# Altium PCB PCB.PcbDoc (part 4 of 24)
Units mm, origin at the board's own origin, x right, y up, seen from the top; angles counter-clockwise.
Board outline 100 x 160 mm, 10 copper layers (TOP_L1, L2, L3, L4, L5, L6, L7, L8, L9, BOTTOM_L10), stack 1.946 mm thick; 1358 components, 1149 nets, 6777 pads, 10914 vias.
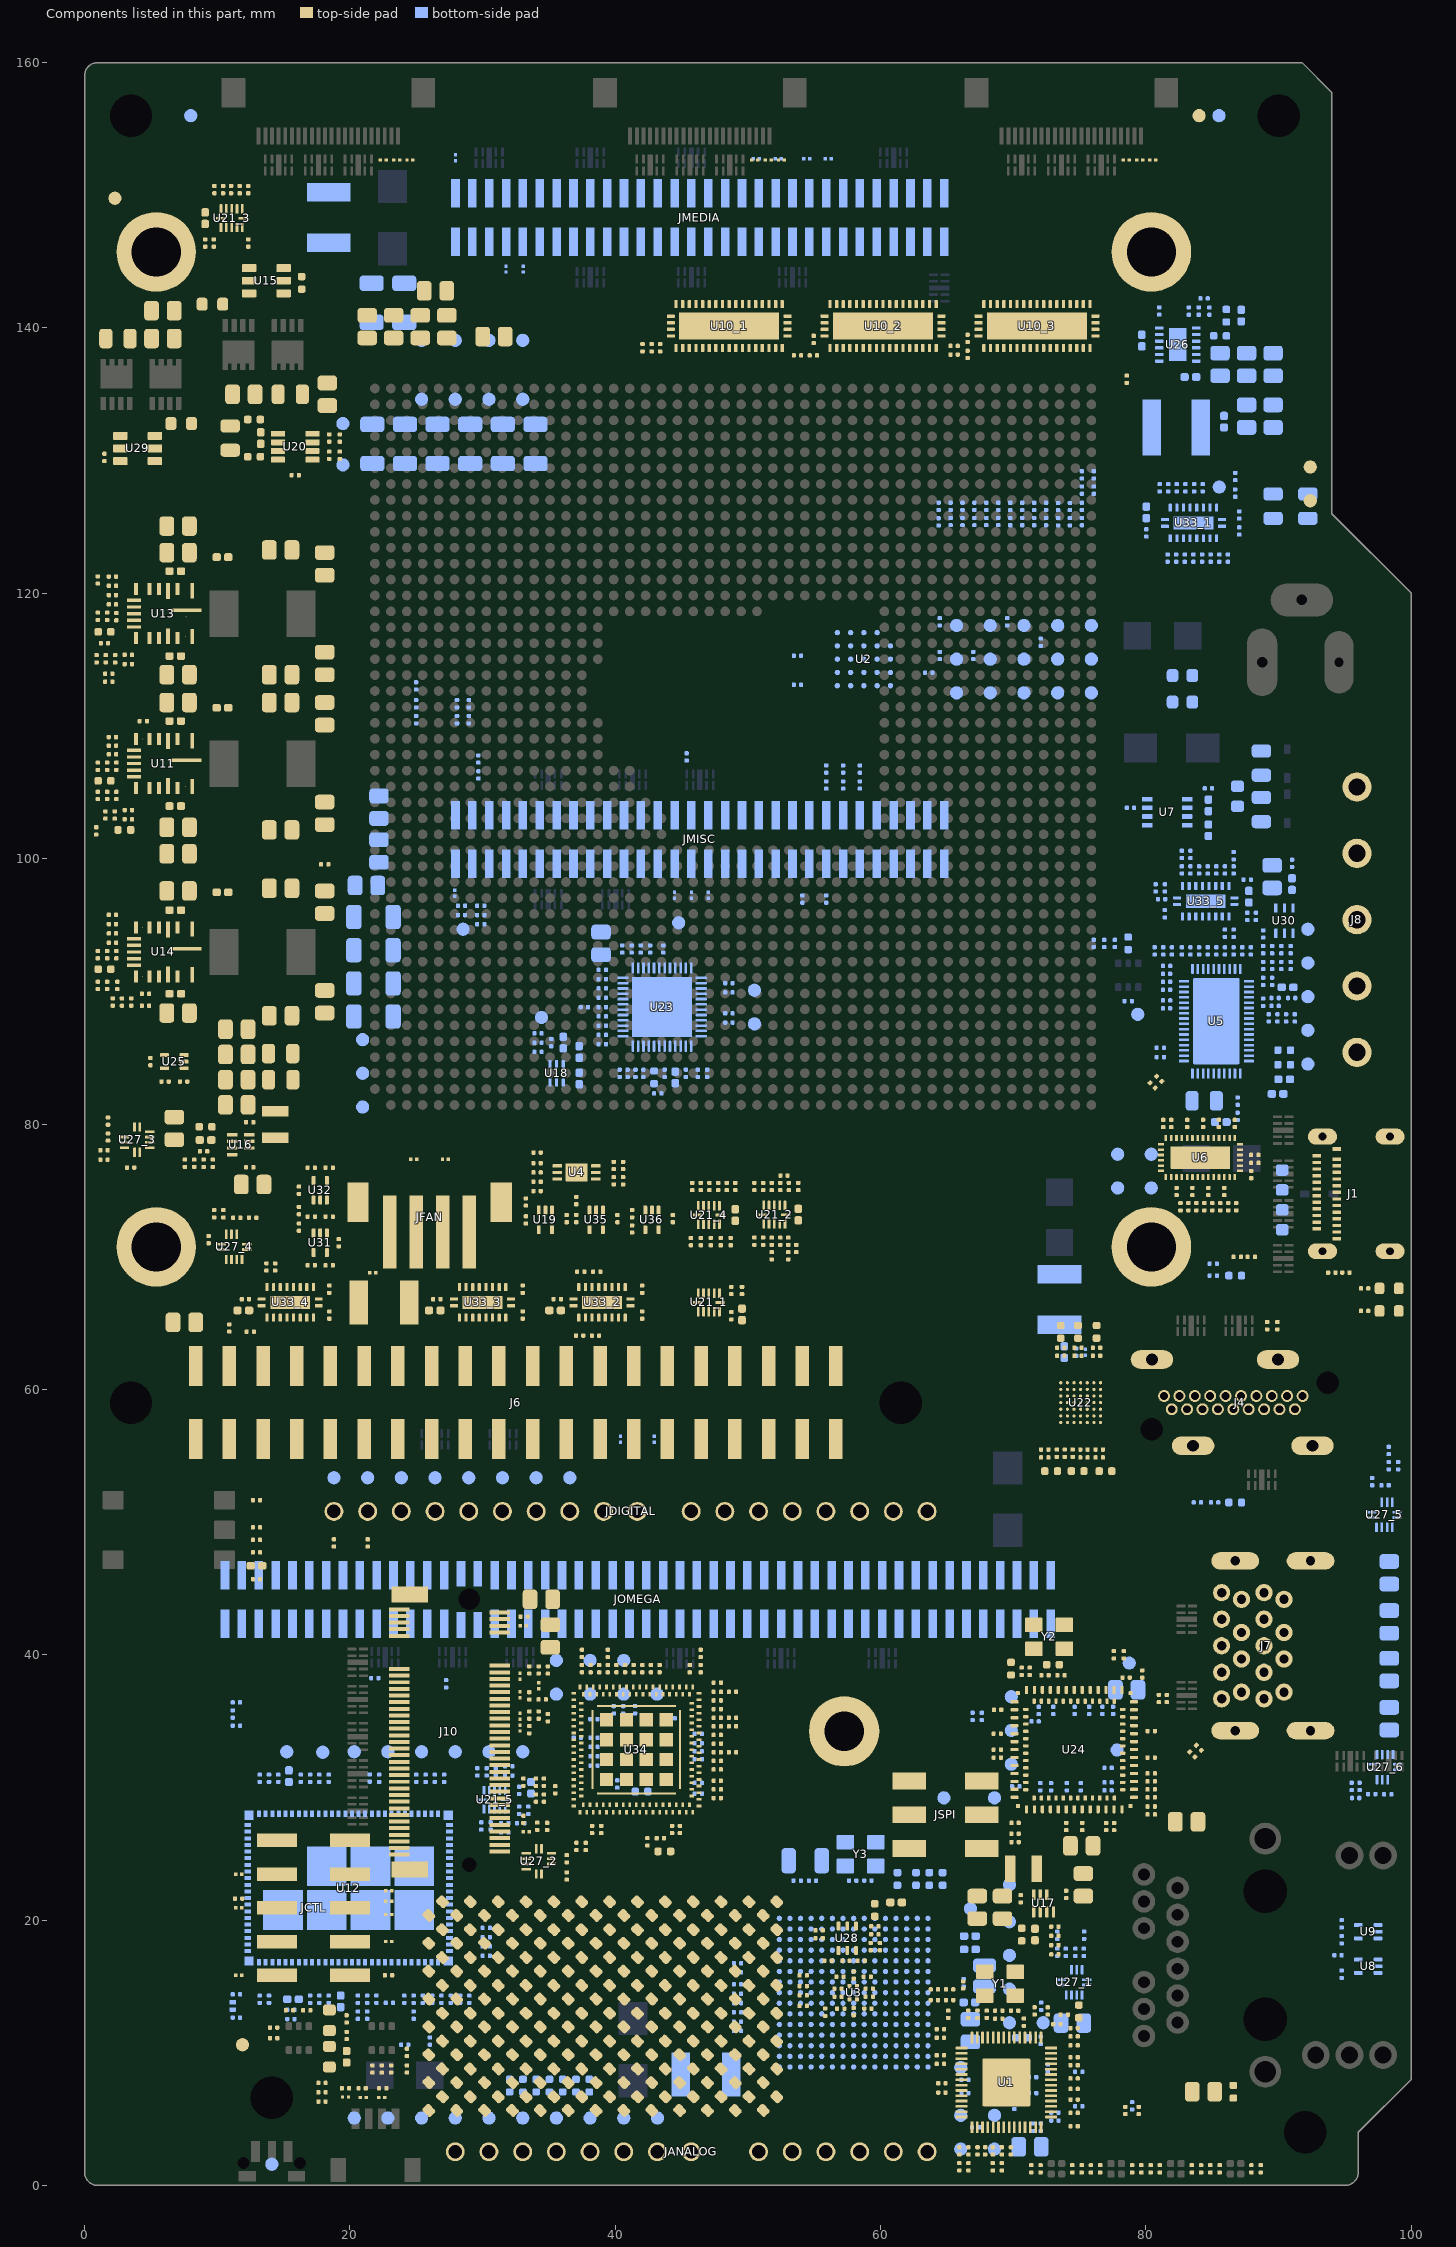
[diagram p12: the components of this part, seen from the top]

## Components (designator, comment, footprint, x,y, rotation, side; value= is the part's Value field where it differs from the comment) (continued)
R235 "CRCW02010000Z0ED" RES-0201 82.703,99.149 r270 bottom value=0
R236 "RC0201FR-0724KL" RES-0201 89.503,91.947 r90 bottom value=24k
R237 "CRCW02010000Z0ED" RES-0201 83.353,99.149 r270 bottom value=0
R238 "RC0201FR-0710KL" RES-0201 1,104.765 r270 top value=10k
R239 "RC0201FR-0710KL" RES-0201 2.3,115.065 r90 top value=10k
R240 "RC0201FR-0710KL" RES-0201 1.6,115.065 r90 top value=10k
R241 "RC0201FR-0710KL" RES-0201 0.9,115.065 r270 top value=10k
R242 "RC0201FR-0710KL" RES-0201 2.469,90.447 r90 top value=10k
R243 "RC0201FR-0710KL" RES-0201 1,90.447 r270 top value=10k
R244 "RC0201FR-07100KL" RES-0201 90.203,91.947 r270 bottom value=100k
R245 "CRCW0402100KFKEDC" RES-0402 16.357,143.393 r90 top value=100k
R246 "AC0201FR-07220KL" RES-0201 90.903,93.142 r90 bottom value=220k
R247 "AC0201FR-07220KL" RES-0201 90.903,91.947 r270 bottom value=220k
R248 "RC0201FR-0724KL" RES-0201 77.657,93.608 r270 bottom value=24k
R249 "RC0201FR-074K7L" RES-0201 78.657,89.265 r180 bottom value=4.7k
R250 "RC0201FR-071KL" RES-0201 87.025,124.7 r90 bottom value=1k
R251 "RC0201FR-071KL" RES-0201 85.525,122.65 r90 bottom value=1k
R252 "RC0201FR-071KL" RES-0201 84.875,122.65 r90 bottom value=1k
R253 "RC0201FR-071KL" RES-0201 84.225,122.65 r90 bottom value=1k
R254 "RC0201FR-071KL" RES-0201 83.575,122.65 r90 bottom value=1k
R255 "RC0201FR-071KL" RES-0201 82.925,122.65 r90 bottom value=1k
R256 "RC0201FR-071KL" RES-0201 82.275,122.65 r90 bottom value=1k
R257 "RC0201FR-071KL" RES-0201 81.625,122.65 r90 bottom value=1k
R258 "RC0201FR-074K7L" RES-0201 17.892,7.024 r180 top value=4.7k
R259 "CRCW02010000Z0ED" RES-0201 18.435,73.02 r180 top value=0
R260 "CRCW02010000Z0ED" RES-0201 18.435,76.71 r0 top value=0
R261 "RC0201FR-0710KL" RES-0201 18.435,69.35 r0 top value=10k
R262 "CRCW02010000Z0ED" RES-0201 17.085,69.35 r0 top value=0
R263 "RC0201FR-0710KL" RES-0201 17.085,76.71 r180 top value=10k
R264 "CRCW02010000Z0ED" RES-0201 16.16,72.225 r270 top value=0
R265 "RC0201FR-0710KL" RES-0201 73.321,18.852 r270 bottom value=10k
R266 "RC0201FR-074K7L" RES-0201 64.504,9.813 r180 top value=4.7k
R267 "RC0201FR-074K7L" RES-0201 64.504,9.163 r0 top value=4.7k
R268 "RC0201FR-071KL" RES-0201 65.537,137.991 r0 top value=1k
R269 "RC0201FR-0710KL" RES-0201 89.902,64.8 r270 top value=10k
R270 "RC0201FR-071KL" RES-0201 37.675,88.816 r180 bottom value=1k
R271 "RC0201FR-0724KL" RES-0201 81.549,90.712 r180 bottom value=24k
R272 "RC0402FR-0710RL" RES-0402 12.774,133.099 r180 top value=10
R273 "RC0402FR-0710RL" RES-0402 12.774,130.299 r180 top value=10
R274 "CRCW02010000Z0ED" RES-0201 89.253,87.997 r90 bottom value=0
R275 "CRCW02010000Z0ED" RES-0201 90.553,87.997 r270 bottom value=0
R276 "CRCW08050000Z0EB" RES-0805 84.388,81.747 r180 bottom value=0
R277 "CRCW02010000Z0ED" RES-0201 39.023,90.916 r0 bottom value=0
R278 "CRCW02010000Z0ED" RES-0201 39.023,90.216 r0 bottom value=0
R279 "CRCW02010000Z0ED" RES-0201 39.023,86.716 r0 bottom value=0
R280 "CRCW02010000Z0ED" RES-0201 39.023,87.416 r0 bottom value=0
R281 "CRCW02010000Z0ED" RES-0201 39.023,88.116 r0 bottom value=0
R282 "CRCW02010000Z0ED" RES-0201 39.023,88.816 r0 bottom value=0
R283 "CRCW02010000Z0ED" RES-0201 39.023,89.516 r0 bottom value=0
R284 "CRCW02010000Z0ED" RES-0201 67.3,12.9 r270 top value=0
R285 "CRCW02010000Z0ED" RES-0201 68,12.9 r270 top value=0
R286 "ERJ-1GNF5101C" RES-0201 48.836,35.249 r0 top value=5.1k
R287 "ERJ-1GNF5101C" RES-0201 39.436,40.099 r90 top value=5.1k
R288 "AC0201FR-07330RL" RES-0201 38.136,38.949 r90 top value=330
R289 "AC0201FR-07330RL" RES-0201 43.336,38.949 r90 top value=330
R290 "AC0201FR-07330RL" RES-0201 38.786,38.949 r90 top value=330
R291 "CRCW02010000Z0ED" RES-0201 34.623,30.391 r90 top value=0
R292 "CRCW02010000Z0ED" RES-0201 34.023,30.391 r90 top value=0
R293 "AC0201FR-07330RL" RES-0201 42.686,38.949 r270 top value=330
R294 "AC0201FR-07330RL" RES-0201 46.255,34.032 r180 bottom value=330
R295 "ERJ-1GNF5101C" RES-0201 37.486,40.099 r90 top value=5.1k
R296 "ERJ-1GNF5101C" RES-0201 34.223,35.45 r270 top value=5.1k
R297 "ERJ-1GNF5101C" RES-0201 48.836,37.199 r0 top value=5.1k
R298 "ERJ-1GNF5101C" RES-0201 48.836,34.599 r0 top value=5.1k
R299 "AC0201FR-07330RL" RES-0201 46.436,38.949 r90 top value=330
R300 "AC0201FR-07330RL" RES-0201 47.686,32.649 r0 top value=330
R301 "AC0201FR-07330RL" RES-0201 47.686,35.249 r0 top value=330
R302 "AC0201FR-07330RL" RES-0201 39.436,38.949 r90 top value=330
R303 "ERJ-1GNF5101C" RES-0201 40.736,38.949 r90 top value=5.1k
R304 "ERJ-1GNF5101C" RES-0201 47.686,33.949 r0 top value=5.1k
R305 "AC0201FR-07330RL" RES-0201 34.923,35.25 r90 top value=330
R306 "AC0201FR-07330RL" RES-0201 47.686,37.199 r0 top value=330
R307 "AC0201FR-07330RL" RES-0201 47.686,34.599 r0 top value=330
R308 "AC0201FR-07330RL" RES-0201 40.086,38.949 r270 top value=330
R309 "AC0201FR-07330RL" RES-0201 47.686,33.299 r180 top value=330
R310 "CRCW02010000Z0ED" RES-0201 47.686,37.899 r0 top value=0
R311 "CRCW02010000Z0ED" RES-0201 47.686,36.549 r0 top value=0
R312 "CRCW02010000Z0ED" RES-0201 25.7,30.685 r270 bottom value=0
R313 "CRCW02010000Z0ED" RES-0201 21.3,14.035 r90 bottom value=0
R314 "CRCW02010000Z0ED" RES-0201 20.6,14.035 r90 bottom value=0
R315 "RC0201FR-0710KL" RES-0201 45.8,75.291 r270 top value=10k
R316 "CRCW02010000Z0ED" RES-0201 13.9,14.035 r90 bottom value=0
R317 "RC0201FR-0710KL" RES-0201 19.75,12.55 r270 top value=10k
R318 "CRCW02010000Z0ED" RES-0201 77.141,30.374 r0 bottom value=0
R319 "RC0201FR-071KL" RES-0201 47.75,75.291 r270 top value=1k
R320 "RC0201FR-071KL" RES-0201 47.1,75.291 r270 top value=1k
R321 "RC0201FR-071KL" RES-0201 46.45,75.291 r270 top value=1k
R322 "RC0201FR-071KL" RES-0201 21.3,12.835 r270 bottom value=1k
R323 "RC0201FR-0710KL" RES-0201 45.7,71.137 r90 top value=10k
R324 "RC0201FR-0710KL" RES-0201 86.603,99.149 r270 bottom value=10k
R325 "RC0201FR-0710KL" RES-0201 86.603,94.372 r270 bottom value=10k
R326_1 "RC0201FR-0710KL" RES-0201 49.55,67.45 r90 top value=10k (schematic designator R326)
R326_2 "RC0201FR-0710KL" RES-0201 53.789,75.291 r270 top value=10k (schematic designator R326)
R326_3 "RC0201FR-0710KL" RES-0201 9.086,146.398 r270 top value=10k (schematic designator R326)
R326_4 "RC0201FR-0710KL" RES-0201 49.05,75.291 r90 top value=10k (schematic designator R326)
R326_5 "RC0201FR-0710KL" RES-0201 33.45,28.27 r270 bottom value=10k (schematic designator R326)
R327 "RC0201FR-0710KL" RES-0201 47.95,71.137 r90 top value=10k
R328 "RC0201FR-0710KL" RES-0201 47.2,71.137 r90 top value=10k
R329 "RC0201FR-0710KL" RES-0201 46.45,71.137 r90 top value=10k
R330 "RC0201FR-071KL" RES-0201 80.726,97.795 r270 bottom value=1k
R331 "RC0201FR-071KL" RES-0201 82.703,100.322 r270 bottom value=1k
R332 "RC0201FR-071KL" RES-0201 83.353,100.322 r270 bottom value=1k
R333 "RC0201FR-074K7L" RES-0201 81.953,93.047 r90 bottom value=4.7k
R334 "RC0201FR-074K7L" RES-0201 82.703,93.047 r90 bottom value=4.7k
R335 "RC0201FR-074K7L" RES-0201 84.003,93.047 r90 bottom value=4.7k
R336 "CRCW02010000Z0ED" RES-0201 12.668,72.936 r180 top value=0
R337 "CRCW02010000Z0ED" RES-0201 1.765,80.219 r270 top value=0
R338 "ERJ-1GNF5101C" RES-0201 9.768,73.236 r90 top value=5.1k
R339 "RC0201FR-0724KL" RES-0201 10.468,73.236 r270 top value=24k
R340 "ERJ-1GNF5101C" RES-0201 1.465,77.319 r180 top value=5.1k
R341 "RC0201FR-0724KL" RES-0201 1.465,78.019 r0 top value=24k
R342 "RC0201FR-0718KL" RES-0201 75.316,17.568 r270 bottom value=18k
R343 "CRCW02010000Z0ED" RES-0201 25.5,14.035 r90 bottom value=0
R344 "CRCW02010000Z0ED" RES-0201 24.8,14.035 r90 bottom value=0
R345 "CRCW02010000Z0ED" RES-0201 22.975,13.76 r0 bottom value=0
R346 "CRCW02010000Z0ED" RES-0201 14.25,11.1 r0 top value=0
R347 "CRCW02010000Z0ED" RES-0201 24.8,12.835 r270 bottom value=0
R348 "CRCW02010000Z0ED" RES-0201 24.1,14.035 r90 bottom value=0
R349 "CRCW02010000Z0ED" RES-0201 0.875,102.091 r270 top value=0
R350 "CRCW02010000Z0ED" RES-0201 33.266,74.123 r270 top value=0
R351 "CRCW02010000Z0ED" RES-0201 54.163,14.329 r0 top value=0
R352 "RC0201FR-07100KL" RES-0201 51.789,70.065 r90 top value=100k
R353 "CRCW02010000Z0ED" RES-0201 22,14.035 r90 bottom value=0
R354 "CRCW02010000Z0ED" RES-0201 2.1,108.515 r0 top value=0
R355 "CRCW02010000Z0ED" RES-0201 2.1,119.865 r0 top value=0
R356 "RC0201FR-0710KL" RES-0201 73.131,17.409 r180 top value=10k
R357 "RC0201FR-0724KL" RES-0201 3.3,102.965 r0 top value=24k
R358 "CRCW02010000Z0ED" RES-0201 2.1,95.066 r0 top value=0
R359 "CRCW02010000Z0ED" RES-0201 1.575,103.291 r90 top value=0
R360 "CRCW02010000Z0ED" RES-0201 1,121.003 r90 top value=0
R361 "CRCW02010000Z0ED" RES-0201 52.439,75.291 r90 top value=0
R362 "CRCW02010000Z0ED" RES-0201 51.789,75.291 r90 top value=0
R363 "CRCW02010000Z0ED" RES-0201 51.139,75.291 r90 top value=0
R364 "CRCW02010000Z0ED" RES-0201 50.489,75.291 r90 top value=0
R365 "CRCW02010000Z0ED" RES-0201 49.211,12.349 r180 bottom value=0
R366 "CRCW02010000Z0ED" RES-0201 49.211,13.049 r180 bottom value=0
R367 "CRCW02010000Z0ED" RES-0201 81.549,91.312 r0 bottom value=0
R368 "CRCW02010000Z0ED" RES-0201 80.653,93.047 r270 bottom value=0
R369 "CRCW02010000Z0ED" RES-0201 81.549,90.112 r0 bottom value=0
R370 "CRCW02010000Z0ED" RES-0201 81.549,91.912 r0 bottom value=0
R371 "RC0201FR-074K7L" RES-0201 21.336,48.425 r270 top value=4.7k
R372 "RC0201FR-074K7L" RES-0201 18.796,48.425 r270 top value=4.7k
R373 "RC0201FR-074K7L" RES-0201 54.109,96.953 r270 bottom value=4.7k
R374 "RC0201FR-074K7L" RES-0201 55.899,96.953 r270 bottom value=4.7k
R375 "RC0201FR-0710KL" RES-0201 20.916,7.324 r180 top value=10k
R376 "RC0201FR-0710KL" RES-0201 22.466,7.324 r0 top value=10k
R377 "CRCW02010000Z0ED" RES-0201 27.6,14.035 r90 bottom value=0
R378 "CRCW02010000Z0ED" RES-0201 26.9,14.035 r90 bottom value=0
R379 "CRCW02010000Z0ED" RES-0201 28.3,14.035 r90 bottom value=0
R380 "CRCW02010000Z0ED" RES-0201 26.2,14.035 r90 bottom value=0
R381 "CRCW02010000Z0ED" RES-0201 29,14.035 r90 bottom value=0
R382 "CRCW02010000Z0ED" RES-0201 80.994,83.406 r315 top value=0
R383 "CRCW02010000Z0ED" RES-0201 80.499,82.911 r315 top value=0
R384 "CRCW02010000Z0ED" RES-0201 49.211,11.649 r0 bottom value=0
R385 "CRCW02010000Z0ED" RES-0201 49.211,16.749 r0 bottom value=0
R386 "RC0201FR-071KL" RES-0201 42.734,138.511 r270 top value=1k
R387 "RC0201FR-071KL" RES-0201 53.731,137.926 r0 top value=1k
R388 "CRCW02010000Z0ED" RES-0201 13.2,30.685 r270 bottom value=0
R389 "RC0201FR-07100KL" RES-0201 10.436,150.425 r90 top value=100k
R390 "RC0201FR-07100KL" RES-0201 11.036,150.425 r90 top value=100k
R391 "RC0201FR-07100KL" RES-0201 11.686,150.425 r90 top value=100k
R392 "RC0201FR-071KL" RES-0201 42.051,138.509 r90 top value=1k
R393 "RC0201FR-071KL" RES-0201 66.551,138.009 r90 top value=1k
R394 "RC0201FR-071KL" RES-0201 78.551,136.134 r270 top value=1k
R395 "RC0201FR-0710KL" RES-0201 12.336,150.425 r90 top value=10k
R396 "RC0201FR-0710KL" RES-0201 12.336,146.398 r90 top value=10k
R397 "RC0201FR-0724KL" RES-0201 76.857,93.608 r90 bottom value=24k
R398 "CRCW0402100KFKEDC" RES-0402 85.58,139.4 r0 bottom value=100k
R399 "CRCW02010000Z0ED" RES-0201 29.858,95.051 r180 bottom value=0
R400 "CRCW02010000Z0ED" RES-0201 28.408,95.751 r0 bottom value=0
R401 "CRCW02010000Z0ED" RES-0201 17.892,6.324 r0 top value=0
R402 "AC0201FR-07220KL" RES-0201 40.582,76.874 r270 top value=220k
R403 "CRCW02010000Z0ED" RES-0201 1.7,106.965 r90 top value=0
R404 "CRCW02010000Z0ED" RES-0201 1.5,116.24 r0 top value=0
R405 "CRCW02010000Z0ED" RES-0201 1.7,92.766 r90 top value=0
R406 "RC0201FR-074K7L" RES-0201 87.634,95.647 r270 bottom value=4.7k
R407 "RC0201FR-074K7L" RES-0201 88.284,95.647 r270 bottom value=4.7k
R408 "CRCW02010000Z0ED" RES-0201 49.211,16.049 r180 bottom value=0
R409 "CRCW02010000Z0ED" RES-0201 49.211,15.149 r180 bottom value=0
R410 "CRCW02010000Z0ED" RES-0201 49.211,13.749 r180 bottom value=0
R411 "CRCW02010000Z0ED" RES-0201 49.211,14.449 r180 bottom value=0
R412 "RC0201FR-071KL" RES-0201 52.714,76.116 r180 top value=1k
R413 "RC0201FR-074K7L" RES-0201 66.6,12.9 r270 top value=4.7k
R414 "RC0201FR-074K7L" RES-0201 86.603,100.222 r270 bottom value=4.7k
R415 "RC0201FR-074K7L" RES-0201 34.923,38.85 r270 top value=4.7k
R416 "RC0201FR-074K7L" RES-0201 34.498,36.625 r0 top value=4.7k
R417 "CRCW02010000Z0ED" RES-0201 33.523,38.85 r90 top value=0
R418 "CRCW02010000Z0ED" RES-0201 34.223,38.85 r90 top value=0
R419 "CRCW02010000Z0ED" RES-0201 33.523,36.9 r270 top value=0
R420 "CRCW0402100KFKEDC" RES-0402 1.5,117.1 r0 top value=100k
R421 "CRCW02010000Z0ED" RES-0201 1.7,118.265 r90 top value=0
R422 "RC0201FR-071KL" RES-0201 14.36,69.225 r270 top value=1k
R423 "RC0201FR-071KL" RES-0201 13.71,69.225 r270 top value=1k
R424 "RC0201FR-071KL" RES-0201 38.6,68.87 r180 top value=1k
R425 "RC0201FR-071KL" RES-0201 37.394,68.87 r0 top value=1k
R426 "RC0201FR-0722K1L" RES-0201 2.4,118.24 r270 top value=22.1k
R427 "CRCW02010000Z0ED" RES-0201 13.2,14.035 r90 bottom value=0
R428 "RC0201FR-0710KL" RES-0201 29.6,31.17 r270 bottom value=10k
R429 "RC0201FR-0710KL" RES-0201 29.9,27.095 r90 bottom value=10k
R430 "CRCW02010000Z0ED" RES-0201 41.262,72.088 r90 top value=0
R431 "RC0201FR-0710KL" RES-0201 37.062,72.873 r270 top value=10k
R432 "RC0201FR-0710KL" RES-0201 41.262,73.238 r270 top value=10k
R433 "CRCW02010000Z0ED" RES-0201 11.61,21.621 r180 top value=0
R434 "CRCW02010000Z0ED" RES-0201 66.213,15.104 r270 top value=0
R435 "CRCW02010000Z0ED" RES-0201 55.813,13.054 r270 top value=0
R436 "AC0201FR-07220KL" RES-0201 94.008,68.8 r180 top value=220k
R437 "AC0201FR-07220KL" RES-0201 95.065,68.8 r0 top value=220k
R438 "CRCW02010000Z0ED" RES-0201 30.275,18.01 r180 bottom value=0
R439 "CRCW02010000Z0ED" RES-0201 30.275,17.31 r180 bottom value=0
R440 "CRCW02010000Z0ED" RES-0201 25,30.685 r270 bottom value=0
R441 "CRCW02010000Z0ED" RES-0201 30.275,19.41 r180 bottom value=0
R442 "CRCW02010000Z0ED" RES-0201 30.275,18.71 r180 bottom value=0
R443 "CRCW02010000Z0ED" RES-0201 18.4,30.685 r270 bottom value=0
R444 "CRCW02010000Z0ED" RES-0201 17.7,30.685 r270 bottom value=0
R445 "CRCW02010000Z0ED" RES-0201 22.2,30.685 r270 bottom value=0
R446 "CRCW02010000Z0ED" RES-0201 21.49,30.702 r270 bottom value=0
R447 "CRCW02010000Z0ED" RES-0201 16.3,30.685 r270 bottom value=0
R448 "CRCW02010000Z0ED" RES-0201 17,30.685 r270 bottom value=0
R449 "AC0201FR-07220KL" RES-0201 87.936,69.985 r0 top value=220k
R450 "AC0201FR-07220KL" RES-0201 86.876,69.985 r180 top value=220k
R451 "CRCW02010000Z0ED" RES-0201 84.4,73.767 r90 top value=0
R452 "CRCW02010000Z0ED" RES-0201 83.8,73.767 r90 top value=0
R453 "CRCW02010000Z0ED" RES-0201 85.6,73.767 r90 top value=0
R454 "CRCW02010000Z0ED" RES-0201 85,73.767 r90 top value=0
R455 "RC0201FR-0710KL" RES-0201 16.16,73.475 r90 top value=10k
R456 "RC0201FR-0710KL" RES-0201 17.085,73.02 r180 top value=10k
R457 "CRCW0603100RFKEAC" RES-0603 18.45,9.7 r90 top value=100
R458 "RC0201FR-071KL" RES-0201 14.25,11.9 r0 top value=1k
R459 "CRCW0603100RFKEAC" RES-0603 18.45,12.45 r270 top value=100
R460 "CRCW0402100KFKEDC" RES-0402 86.05,140.925 r270 bottom value=100k
R461 "RC0201FR-0710KL" RES-0201 30.6,27.095 r90 bottom value=10k
R462 "CRCW02010000Z0ED" RES-0201 27.1,30.685 r270 bottom value=0
R463 "RC0201FR-0710KL" RES-0201 31,31.17 r270 bottom value=10k
R464 "RC0201FR-0710KL" RES-0201 31.975,31.595 r180 bottom value=10k
R465 "RC0201FR-074K7L" RES-0201 31.675,27.307 r0 bottom value=4.7k
R466 "RC0201FR-074K7L" RES-0201 31.675,26.607 r180 bottom value=4.7k
R467 "RC0201FR-0710KL" RES-0201 31.975,30.895 r180 bottom value=10k
R468 "RC0201FR-0710KL" RES-0201 20.6,12.835 r90 bottom value=10k
R469 "CRCW02010000Z0ED" RES-0201 17.7,14.035 r270 bottom value=0
R470 "CRCW02010000Z0ED" RES-0201 17,14.035 r270 bottom value=0
R471 "CRCW02010000Z0ED" RES-0201 26.4,30.685 r90 bottom value=0
R472 "RC0201FR-0724KL" RES-0201 76.057,93.608 r270 bottom value=24k
R473 "RC0201FR-0724KL" RES-0201 95.8,29.2 r0 bottom value=24k
R474 "RC0201FR-0724KL" RES-0201 98.298,55.396 r270 bottom value=24k
R475 "CRCW02010000Z0ED" RES-0201 86.903,81.722 r90 bottom value=0
R476 "CRCW02010000Z0ED" RES-0201 86.903,80.572 r270 bottom value=0
R477 "CRCW02010000Z0ED" RES-0201 12.957,48.653 r180 top value=0
R478 "RC0201FR-074K7L" RES-0201 12.957,47.709 r0 top value=4.7k
R479 "CRCW02010000Z0ED" RES-0201 12.957,49.597 r0 top value=0
R480 "CRCW02010000Z0ED" RES-0201 4.425,110.365 r0 top value=0
R481 "CRCW02010000Z0ED" RES-0201 45.374,107.667 r270 bottom value=0
R482 "CRCW02010000Z0ED" RES-0201 12.957,45.7 r0 top value=0
R483 "RC0201FR-075M6L" RES-0201 24.3,8.775 r90 top value=5.6M
R484 "CRCW02010000Z0ED" RES-0201 19.75,11.3 r90 top value=0
R485 "CRCW02010000Z0ED" RES-0201 24.3,10.025 r270 top value=0
R486 "CRCW02010000Z0ED" RES-0201 22.91,15.841 r180 top value=0
R487 "RC0201FR-0710KL" RES-0201 7.465,83.202 r180 top value=10k
R488 "CRCW02010000Z0ED" RES-0201 21.877,38.243 r0 bottom value=0
R489 "RC0201FR-0710KL" RES-0201 33.266,72.773 r90 top value=10k
R490 "AF0402FR-072K2L" RES-0402 86.72,68.575 r0 bottom value=2.2k
R491 "AF0402FR-072K2L" RES-0402 86.72,51.475 r0 bottom value=2.2k
R492 "CRCW02010000Z0ED" RES-0201 85.07,68.575 r180 bottom value=0
R493 "CRCW02010000Z0ED" RES-0201 85.07,69.475 r180 bottom value=0
R494 "CRCW02010000Z0ED" RES-0201 85.17,51.475 r180 bottom value=0
R495 "CRCW02010000Z0ED" RES-0201 83.87,51.475 r180 bottom value=0
R496 "CRCW02010000Z0ED" RES-0201 4.594,89.816 r180 top value=0
R497 "CRCW02010000Z0ED" RES-0201 4.594,88.916 r180 top value=0
R498 "RC0201FR-07100KL" RES-0201 84.78,141.27 r90 bottom value=100k
R499 "CRCW02010000Z0ED" RES-0201 81,141.275 r270 bottom value=0
R500 "CRCW020131K6FKED" RES-0201 83.23,141.27 r270 bottom value=31.6k
R501 "CRCW02010000Z0ED" RES-0201 90.203,93.142 r90 bottom value=0
R502 "CRCW08050000Z0EB" RES-0805 89.58,126.565 r270 bottom value=0
R503 "RC0201FR-071KL" RES-0201 84.38,142.22 r0 bottom value=1k
R504 "CRCW02010000Z0ED" RES-0201 91.005,99.645 r90 bottom value=0
R505 "CRCW08050000Z0EB" RES-0805 92.2,126.565 r270 bottom value=0
R506 "RT0805FRE0760R4L" RES-0805 88.7,103.7 r270 bottom value=60.4
R507 "RT0805FRE0760R4L" RES-0805 88.7,107.2 r270 bottom value=60.4
R508 "CRCW02010000Z0ED" RES-0201 29.858,95.751 r0 bottom value=0
R509 "CRCW02010000Z0ED" RES-0201 29.858,96.451 r0 bottom value=0
R510 "CRCW02010000Z0ED" RES-0201 24.13,10.6 r180 bottom value=0
R511 "RC0201FR-075M6L" RES-0201 26.03,10.875 r270 bottom value=5.6M
TP1 "Test point 1.00mm" TP-1.00MM 21.336,53.34 r270 bottom
TP2 "Test point 1.00mm" TP-1.00MM 80.401,75.181 r315 bottom
TP3 "Test point 1.00mm" TP-1.00MM 80.401,77.721 r315 bottom
TP4 "Test point 1.00mm" TP-1.00MM 77.861,75.181 r90 bottom
TP5 "Test point 1.00mm" TP-1.00MM 77.861,77.721 r90 bottom
TP6 "Test point 1.00mm" TP-1.00MM 64.77,29.21 r90 bottom
TP7 "Test point 1.00mm" TP-1.00MM 68.58,29.21 r90 bottom
TP8 "Test point 1.00mm" TP-1.00MM 69.85,36.83 r90 bottom
TP9 "Test point 1.00mm" TP-1.00MM 69.85,34.29 r90 bottom
TP10 "Test point 1.00mm" TP-1.00MM 69.85,31.75 r90 bottom
TP11 "Test point 1.00mm" TP-1.00MM 78.74,39.37 r90 bottom
TP12 "Test point 1.00mm" TP-1.00MM 77.823,32.816 r90 bottom
TP13 "Test point 1.00mm" TP-1.00MM 35.56,39.57 r90 bottom
TP14 "Test point 1.00mm" TP-1.00MM 35.56,37.03 r90 bottom
TP15 "Test point 1.00mm" TP-1.00MM 30.48,32.68 r90 bottom
TP16 "Test point 1.00mm" TP-1.00MM 33.02,32.68 r90 bottom
TP17 "Test point 1.00mm" TP-1.00MM 20.32,32.68 r90 bottom
TP18 "Test point 1.00mm" TP-1.00MM 27.94,32.68 r90 bottom
TP19 "Test point 1.00mm" TP-1.00MM 43.145,37.03 r90 bottom
TP20 "Test point 1.00mm" TP-1.00MM 40.64,37.03 r90 bottom
TP21 "Test point 1.00mm" TP-1.00MM 38.1,37.03 r90 bottom
TP22 "Test point 1.00mm" TP-1.00MM 40.64,39.57 r90 bottom
TP23 "Test point 1.00mm" TP-1.00MM 38.1,39.57 r90 bottom
TP24 "Test point 1.00mm" TP-1.00MM 22.86,32.68 r90 bottom
TP25 "Test point 1.00mm" TP-1.00MM 65.722,115.036 r0 bottom
TP26 "Test point 1.00mm" TP-1.00MM 65.722,117.576 r0 bottom
TP27 "Test point 1.00mm" TP-1.00MM 68.262,115.036 r0 bottom
TP28 "Test point 1.00mm" TP-1.00MM 73.342,115.036 r180 bottom
TP29 "Test point 1.00mm" TP-1.00MM 92.2,94.68 r180 bottom
TP30 "Test point 1.00mm" TP-1.00MM 18.796,53.34 r270 bottom
TP31 "Test point 1.00mm" TP-1.00MM 70.802,112.496 r0 bottom
TP32 "Test point 1.00mm" TP-1.00MM 92.38,126.98 r180 top
TP33 "Test point 1.00mm" TP-1.00MM 20.955,83.82 r90 bottom
TP34 "Test point 1.00mm" TP-1.00MM 28.529,94.676 r270 bottom
TP35 "Test point 1.00mm" TP-1.00MM 33.02,5.08 r90 bottom
TP36 "Test point 1.00mm" TP-1.00MM 92.2,92.14 r180 bottom
TP37 "Test point 1.00mm" TP-1.00MM 92.2,89.6 r180 bottom
TP38 "Test point 1.00mm" TP-1.00MM 92.2,87.06 r180 bottom
TP39 "Test point 1.00mm" TP-1.00MM 92.2,84.52 r180 bottom
TP40 "Test point 1.00mm" TP-1.00MM 68.58,2.74 r90 bottom
TP41 "Test point 1.00mm" TP-1.00MM 69.71,14.798 r90 bottom
TP42 "Test point 1.00mm" TP-1.00MM 69.71,12.258 r90 bottom
TP43 "Test point 1.00mm" TP-1.00MM 72.25,12.258 r90 bottom
TP44 "Test point 1.00mm" TP-1.00MM 69.71,19.878 r90 bottom
TP45 "Test point 1.00mm" TP-1.00MM 69.71,17.338 r90 bottom
TP46 "Test point 1.00mm" TP-1.00MM 66.04,2.74 r90 bottom
TP47 "Test point 1.00mm" TP-1.00MM 66.04,5.28 r90 bottom
TP48 "Test point 1.00mm" TP-1.00MM 68.58,5.28 r90 bottom
TP49 "Test point 1.00mm" TP-1.00MM 66.04,8.89 r90 bottom
TP50 "Test point 1.00mm" TP-1.00MM 73.342,117.576 r0 bottom
TP51 "Test point 1.00mm" TP-1.00MM 75.882,115.036 r180 bottom
TP52 "Test point 1.00mm" TP-1.00MM 70.802,117.576 r0 bottom
TP53 "Test point 1.00mm" TP-1.00MM 70.802,115.036 r0 bottom
TP54 "Test point 1.00mm" TP-1.00MM 68.262,112.496 r0 bottom
TP55 "Test point 1.00mm" TP-1.00MM 73.342,112.496 r0 bottom
TP56 "Test point 1.00mm" TP-1.00MM 75.882,112.496 r0 bottom
TP57 "Test point 1.00mm" TP-1.00MM 75.882,117.576 r0 bottom
TP58 "Test point 1.00mm" TP-1.00MM 15.24,32.68 r90 bottom
TP59 "Test point 1.00mm" TP-1.00MM 17.952,32.644 r90 bottom
TP60 "Test point 1.00mm" TP-1.00MM 19.469,132.793 r90 bottom
TP61 "Test point 1.00mm" TP-1.00MM 36.576,53.34 r90 bottom
TP62 "Test point 1.00mm" TP-1.00MM 34.036,53.34 r90 bottom
TP63 "Test point 1.00mm" TP-1.00MM 31.496,53.34 r90 bottom
TP64 "Test point 1.00mm" TP-1.00MM 28.956,53.34 r90 bottom
TP65 "Test point 1.00mm" TP-1.00MM 26.416,53.34 r90 bottom
TP66 "Test point 1.00mm" TP-1.00MM 23.876,53.34 r90 bottom
TP67 "Test point 1.00mm" TP-1.00MM 27.94,5.08 r90 bottom
TP68 "Test point 1.00mm" TP-1.00MM 30.48,5.08 r90 bottom
TP69 "Test point 1.00mm" TP-1.00MM 19.473,129.68 r90 bottom
TP70 "Test point 1.00mm" TP-1.00MM 35.56,5.08 r90 bottom
TP71 "Test point 1.00mm" TP-1.00MM 38.1,5.08 r90 bottom
TP72 "Test point 1.00mm" TP-1.00MM 40.64,5.08 r90 bottom
TP73 "Test point 1.00mm" TP-1.00MM 43.18,5.08 r90 bottom
TP74 "Test point 1.00mm" TP-1.00MM 33.02,134.62 r270 bottom
TP75 "Test point 1.00mm" TP-1.00MM 30.48,134.62 r270 bottom
TP76 "Test point 1.00mm" TP-1.00MM 27.94,134.62 r270 bottom
TP77 "Test point 1.00mm" TP-1.00MM 25.4,134.62 r270 bottom
TP78 "Test point 1.00mm" TP-1.00MM 27.94,139.065 r0 bottom
TP79 "Test point 1.00mm" TP-1.00MM 25.4,139.065 r0 bottom
TP80 "Test point 1.00mm" TP-1.00MM 30.48,139.065 r0 bottom
TP81 "Test point 1.00mm" TP-1.00MM 33.02,139.065 r0 bottom
TP82 "Test point 1.00mm" TP-1.00MM 79.375,88.265 r90 bottom
TP83 "Test point 1.00mm" TP-1.00MM 20.955,86.36 r90 bottom
TP84 "Test point 1.00mm" TP-1.00MM 20.955,81.28 r90 bottom
TP85 "Test point 1.00mm" TP-1.00MM 34.44,88.03 r90 bottom
TP86 "Test point 1.00mm" TP-1.00MM 66.768,20.863 r90 bottom
TP87 "Test point 1.00mm" TP-1.00MM 25.4,32.68 r90 bottom
TP88 "Test point 1.00mm" TP-1.00MM 85.525,128.008 r90 bottom
TP89 "Test point 1.00mm" TP-1.00MM 50.489,90.086 r0 bottom
TP90 "Test point 1.00mm" TP-1.00MM 22.86,5.08 r90 bottom
TP91 "Test point 1.00mm" TP-1.00MM 20.32,5.08 r90 bottom
TP92 "Test point 1.00mm" TP-1.00MM 25.4,5.08 r90 bottom
TP93 "Test point 1.00mm" TP-1.00MM 92.38,129.52 r180 top
TP94 "Test point 1.00mm" TP-1.00MM 50.489,87.546 r0 bottom
TP95 "Test point 1.00mm" TP-1.00MM 44.774,95.166 r90 bottom
TP_FLASH_SAIL_1V8 "Test point 1.00mm" TP-1.00MM 68.262,117.576 r0 bottom
TP_FLASH_SAIL_GND "Test point 1.00mm" TP-1.00MM 65.722,112.496 r0 bottom
U1 "QCA8081" "Qualcomm QCA8081 56 MQFN 7x7mm pitch 0.4mm" 69.481,7.759 r180 top locked
U2 "MX25UW25345GXDI00-TR" MX25UW25345GXDI00-TR 58.737,115.036 r180 bottom
U3 "STM32H5F5LJH7Q" BGA225C80P15X15_1300X1300X120 57.963,14.529 r270 bottom locked
U4 "LTC6993CDCB-1#TRMPBF" "AD DCB DFN 6 pin 2x3mm pitch 0.5mm" 37.082,76.349 r0 top
U5 "CYPD6129-52LQXI" "QFN52 pitch 0.4mm, 5x8mm" 85.303,87.747 r0 bottom
U6 "TMUXHS4446RETT" "TI QWFN40 RET0040A Pitch 0.4mm 3x6mm" 84.1,77.465 r270 top
U7 "ATA6563-GBQW1" "Microchip VDFN8 pitch 0.65mm 3x3mm exposed pad 2.4x1.6mm" 81.603,103.503 r0 bottom
U8 "SN74LVC1G07DRLR" "TI DRL DRL0005A" 96.741,16.519 r180 bottom
U9 "SN74LVC1G07DRLR" "TI DRL DRL0005A" 96.741,19.119 r180 bottom
U10_1 "TS3DV642A0RUAR" "TI RUA0042A WQFN 42 pin pitch 0.5mm 3.5x9mm" 48.582,140.141 r90 top (schematic designator U10)
U10_2 "TS3DV642A0RUAR" "TI RUA0042A WQFN 42 pin pitch 0.5mm 3.5x9mm" 60.182,140.141 r90 top (schematic designator U10)
U10_3 "TS3DV642A0RUAR" "TI RUA0042A WQFN 42 pin pitch 0.5mm 3.5x9mm" 71.782,140.141 r90 top (schematic designator U10)
U11 "MPQ4371GVE-1001-AECC901-Z" MPQ4371GVE-1001-AECC901-Z 6,107.165 r90 top
U12 "NFA725B" NFA725B 19.9,22.41 r270 bottom locked
U13 "MPQ4371GVE-1001-AECC901-Z" MPQ4371GVE-1001-AECC901-Z 6,118.465 r90 top
U14 "MPQ4371GVE-1001-AECC901-Z" MPQ4371GVE-1001-AECC901-Z 6,92.966 r90 top
U15 "KTS1900GXAA-TA" "SOT23-6 PITCH 0.95" 13.7,143.558 r180 top
U16 "MPQ2179GQHE-AEC1-C901-Z" "MPS QFN8 pitch 0.5mm 1.5x2x1mm" 11.768,78.441 r180 top
U17 "MPQ2179GQHE-AEC1-C901-Z" "MPS QFN8 pitch 0.5mm 1.5x2x1mm" 72.281,21.259 r270 top
U18 "MP20312GTF-0000" SOT563 35.575,83.831 r270 bottom
U19 "SN74LVC1G07DRLR" "TI DRL DRL0005A" 34.732,72.773 r270 top
U20 "INA232AIDDFR" "TI DDF SOT23-THIN 8 pin 1.6x2.9x1.1 mm heigth" 15.874,131.049 r0 top
U21_1 "TXS0104ERUTR" "TI RUT RUT0012A UQFN 2x1.7x0.55mm 12 pins 0.4mm pitch" 47.05,66.55 r270 top (schematic designator U21)
U21_2 "TXS0104ERUTR" "TI RUT RUT0012A UQFN 2x1.7x0.55mm 12 pins 0.4mm pitch" 51.989,73.169 r270 top (schematic designator U21)
U21_3 "TXS0104ERUTR" "TI RUT RUT0012A UQFN 2x1.7x0.55mm 12 pins 0.4mm pitch" 11.086,148.275 r90 top (schematic designator U21)
U21_4 "TXS0104ERUTR" "TI RUT RUT0012A UQFN 2x1.7x0.55mm 12 pins 0.4mm pitch" 47.05,73.141 r270 top (schematic designator U21)
U21_5 "TXS0104ERUTR" "TI RUT RUT0012A UQFN 2x1.7x0.55mm 12 pins 0.4mm pitch" 30.9,29.07 r90 bottom (schematic designator U21)
U22 "ADV7535BCBZ-RL" "Analog Devices CB-49-1 WLCSP49 7x7 pitch 0.5mm 3.5x3.5mm" 75.075,59 r270 top
U23 "MAX98091ETM+T" QFN127P600-8N 43.523,88.816 r270 bottom
U24 "TUSB7340RKMR" "TI RKM S-PWQFN-N100 Double row 9x9mm pitch 0.6mm" 74.591,32.849 r270 top locked
U25 "SN74LVC1G07DRLR" "TI DRL DRL0005A" 6.765,84.702 r180 top
U26 "LMR51440SDRRR" "WSON8 TI DDR 3x3mm 12 pins pitch 0.5mm" 82.39,138.75 r0 bottom
U27_1 "MP5077GG-Z" "MPS QFN12 2x2mm pitch 0.4mm" 74.581,15.309 r270 bottom (schematic designator U27)
U27_2 "MP5077GG-Z" "MPS QFN12 2x2mm pitch 0.4mm" 34.241,24.424 r180 top (schematic designator U27)
U27_3 "MP5077GG-Z" "MPS QFN12 2x2mm pitch 0.4mm" 3.965,78.819 r0 top (schematic designator U27)
U27_4 "MP5077GG-Z" "MPS QFN12 2x2mm pitch 0.4mm" 11.268,70.736 r270 top (schematic designator U27)
U27_5 "MP5077GG-Z" "MPS QFN12 2x2mm pitch 0.4mm" 97.971,50.546 r270 bottom (schematic designator U27)
U27_6 "MP5077GG-Z" "MPS QFN12 2x2mm pitch 0.4mm" 98.015,31.535 r90 bottom (schematic designator U27)
U28 "SGM3157YC6/TR" TSOP65P210X110-6N 57.483,18.629 r270 top
U29 "KTS1900GXAA-TA" "SOT23-6 PITCH 0.95" 4,130.915 r0 top
U30 "MP2013GG-Z" "MPS QNF6 2x2mm 6pin pitch 0.65mm thermal pad" 90.433,95.323 r270 bottom
U31 "SN74LVC1G07DRLR" "TI DRL DRL0005A" 17.76,71.05 r270 top
U32 "SN74LVC1G07DRLR" "TI DRL DRL0005A" 17.76,75.01 r90 top
U33_1 "TXS0108ERKSR" QFN50P250X450X100_HS-21N 83.575,125.3 r90 bottom (schematic designator U33)
U33_2 "TXS0108ERKSR" QFN50P250X450X100_HS-21N 39,66.55 r270 top (schematic designator U33)
U33_3 "TXS0108ERKSR" QFN50P250X450X100_HS-21N 30,66.55 r270 top (schematic designator U33)
U33_4 "TXS0108ERKSR" QFN50P250X450X100_HS-21N 15.5,66.55 r270 top (schematic designator U33)
U33_5 "TXS0108ERKSR" QFN50P250X450X100_HS-21N 84.503,96.795 r270 bottom (schematic designator U33)
U34 "PI7C9X2G304EV" PI7C9X2G304EV-Footprint-1 41.591,32.849 r180 top locked
U35 "SN74LVC1G07DRLR" "TI DRL DRL0005A" 38.562,72.773 r270 top
U36 "SN74LVC1G07DRLR" "TI DRL DRL0005A" 42.762,72.773 r270 top
Y1 "CX3225FB50000F0FZZH1" CRYSTAL3.2X2.5 69,15.2 r180 top
Y2 "CX3225FB48000F0FZZH1" CRYSTAL3.2X2.5 72.691,41.349 r0 top
Y3 "ECS-480-8-33B2-CKM-TR3" CRYSTAL3.2X2.5 58.488,24.974 r180 bottom locked
Y4 "CM315D32768DZFT" ABS07 54.313,24.475 r180 bottom locked

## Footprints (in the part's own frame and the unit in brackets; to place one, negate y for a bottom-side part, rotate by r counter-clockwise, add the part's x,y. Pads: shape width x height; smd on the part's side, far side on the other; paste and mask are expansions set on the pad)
1X14-CUSTOM [mil]
  round 56 hole 40.16: 1(-700,0) 2(-600,0) 3(-500,0) 4(-400,0) 5(-300,0) 6(-200,0) 7(-100,0) 8(0,0) 9(200,0) 10(300,0) 11(400,0) 12(500,0) 13(600,0) 14(700,0)
  body extent -760,-50 759,50, height 335
1X18-CUSTOM [mil]
  round 56 hole 40.16: 1(-700,0) 2(-600,0) 3(-500,0) 4(-400,0) 5(-300,0) 6(-200,0) 7(-100,0) 8(0,0) 9(160,0) 10(260,0) 11(360,0) 12(460,0) 13(560,0) 14(660,0) 15(760,0) 16(860,0) 17(960,0) 18(1060,0)
  body extent -758,-50 1120,50, height 335
19PF-P3-S297 [mm]
  round 0.9 hole 0.6 mask+0.05: 1(0.5,-4.725) 2(-0.5,-4.145) 3(0.5,-3.565) 4(-0.5,-2.985) 5(0.5,-2.405) 6(-0.5,-1.825) 7(0.5,-1.245) 8(-0.5,-0.665) 9(0.5,-0.085) 10(-0.5,0.495) 11(0.5,1.075) 12(-0.5,1.655) 13(0.5,2.235) 14(-0.5,2.815) 15(0.5,3.395) 16(-0.5,3.975) 17(0.5,4.555) 18(-0.5,5.135) 19(0.5,5.715)
  round 1.35 hole 1.7 unplated mask+0.05: NC(-2,6.625) NC(1.5,-6.625)
  oval 1.4x3.2 hole 0.9 slot 2.7 at 90 deg mask+0.05: SH1(-3.25,3.525) SH2(-3.25,-5.475) SH3(3.25,-2.875) SH4(3.25,6.625)
  body extent -3.9,-15.13 3.85,7.93, height 16.4
20TW-638 [mm]
  rect 1.02x3 smd: 1(-5.08,-2.75) 2(-5.08,2.75) 3(-2.54,-2.75) 4(-2.54,2.75) 5(0,-2.75) 6(0,2.75) 7(2.54,-2.75) 8(2.54,2.75) 9(5.08,-2.75) 10(5.08,2.75)
  body extent -6.35,-3.65 6.35,3.65, height 9.7
23TW-018 [mm]
  rect 1.02x3 smd: 1(-24.13,-2.75) 2(-24.13,2.75) 3(-21.59,-2.75) 4(-21.59,2.75) 5(-19.05,-2.75) 6(-19.05,2.75) 7(-16.51,-2.75) 8(-16.51,2.75) 9(-13.97,-2.75) 10(-13.97,2.75) 11(-11.43,-2.75) 12(-11.43,2.75) 13(-8.89,-2.75) 14(-8.89,2.75) 15(-6.35,-2.75) 16(-6.35,2.75) 17(-3.81,-2.75) 18(-3.81,2.75) 19(-1.27,-2.75) 20(-1.27,2.75) 21(1.27,-2.75) 22(1.27,2.75) 23(3.81,-2.75) 24(3.81,2.75) 25(6.35,-2.75) 26(6.35,2.75) 27(8.89,-2.75) 28(8.89,2.75) 29(11.43,-2.75) 30(11.43,2.75) 31(13.97,-2.75) 32(13.97,2.75) 33(16.51,-2.75) 34(16.51,2.75) 35(19.05,-2.75) 36(19.05,2.75) 37(21.59,-2.75) 38(21.59,2.75) 39(24.13,-2.75) 40(24.13,2.75)
  body extent -25.4,-3.65 25.4,3.65, height 9.7
23TW-025 [mm]
  rect 1.27x2.54 smd: 1(-2.54,-2.73) 2(-2.54,2.73) 3(0,-2.73) 4(0,2.73) 5(2.54,-2.73) 6(2.54,2.73)
  silkscreen extent -3.89,-2.78 -3.79,-2.68, body extent -3.81,-3.75 3.81,3.75, height 9
"0201DS Coilcraft" [mm] "Chip Inductor, 2-Leads, Body 0201 (in) 0603 (mm) IPC Medium Density"
  rrect10% 0.33x0.46 smd mask+0.05: 1(-0.275,0) 2(0.275,0)
  body extent -0.29,-0.2 0.29,0.2, height 0.5
209B-DA12 [mm]
  round 1.3 hole 0.7 mask+0.05: 1(-3.5,2) 2(-1,2) 3(1,2) 4(3.5,2) 5(4,3.5) 6(2,3.5) 7(0,3.5) 8(-2,3.5) 9(-4,3.5) 10(-3.5,5.2) 11(-1,5.2) 12(1,5.2) 13(3.5,5.2) 14(4,6.7) 15(2,6.7) 16(0,6.7) 17(-2,6.7) 18(-4,6.7)
  oval 1.3x3.6 hole 0.7 slot 3 at 90 deg mask+0.1: 19(-6.4,5.68) 20(-6.4,0) 21(6.4,0) 22(6.4,5.68)
  body extent -7.5,-9.5 7.5,7.95, height 16.39
1812 [mm] "Chip Capacitor, Body 4.5x3.2mm, IPC High Density"
  rect 1.4x3.3 smd: 1(-1.9,0) 2(1.9,0)
  body extent -2.4,-1.7 2.4,1.7, height 1.4
9774040243R [mm]
  round 5.3 hole 3 mask+0.1: 1(0,0)
  body extent -2.19,-2.17 2.16,2.15, height 4.1
9774050151R [mm]
  round 6 hole 3.7 mask+0.1: 1(0,0)
  body extent -2.6,-2.57 2.5,2.53, height 5
ABS07 [mm]
  rrect50% 1.1x1.9 smd: 1(-1.25,0) 2(1.25,0)
  body extent -1.65,-0.83 1.65,0.83, height 0.9
"AD DCB DFN 6 pin 2x3mm pitch 0.5mm" [mm] "PQFN, 6-Leads, Body 2.00x3.00mm, Pitch 0.50mm, Thermal Pad 1.35x1.65mm, IPC Medium Density"
  rrect25% 0.7x0.25 smd mask+0.05: 1(-1.45,0.5) 2(-1.45,0) 3(-1.45,-0.5) 4(1.45,-0.5) 5(1.45,0) 6(1.45,0.5)
  rrect5% 1.65x1.35 smd paste-2539.97 mask+0.05: 7(0,0)
  silkscreen extent -1.7,1.09 -1.6,1.19, body extent -1.48,-1 1.5,1, height 0.82
"Analog Devices CB-49-1 WLCSP49 7x7 pitch 0.5mm 3.5x3.5mm" [mm]
  round 0.24 smd mask+0.05: A1(-1.5,1.5) A2(-1,1.5) A3(-0.5,1.5) A4(0,1.5) A5(0.5,1.5) A6(1,1.5) A7(1.5,1.5) B1(-1.5,1) B2(-1,1) B3(-0.5,1) B4(0,1) B5(0.5,1) B6(1,1) B7(1.5,1) C1(-1.5,0.5) C2(-1,0.5) C3(-0.5,0.5) C4(0,0.5) C5(0.5,0.5) C6(1,0.5) C7(1.5,0.5) D1(-1.5,0) D2(-1,0) D3(-0.5,0) D4(0,0) D5(0.5,0) D6(1,0) D7(1.5,0) E1(-1.5,-0.5) E2(-1,-0.5) E3(-0.5,-0.5) E4(0,-0.5) E5(0.5,-0.5) E6(1,-0.5) E7(1.5,-0.5) F1(-1.5,-1) F2(-1,-1) F3(-0.5,-1) F4(0,-1) F5(0.5,-1) F6(1,-1) F7(1.5,-1) G1(-1.5,-1.5) G2(-1,-1.5) G3(-0.5,-1.5) G4(0,-1.5) G5(0.5,-1.5) G6(1,-1.5) G7(1.5,-1.5)
  silkscreen extent -1.99,1.89 -1.89,1.99, body extent -1.73,-1.73 1.73,1.73, height 0.66
B4B-PH-SM4-TB(LF)(SN) [mm]
  rect 1x5.5 smd mask+0.1: 1(3,2.25) 2(1,2.25) 3(-1,2.25) 4(-3,2.25)
  rect 1.6x3 smd mask+0.1: FIX(-5.4,0) FIX(5.4,0)
  body extent -5.97,-2.5 5.98,4.5, height 6.6
BGA225C80P15X15_1300X1300X120 [mm] "BGA, 225-Leads, Body 13,00x13,00mmx1,20mm, Pitch 0,80mm"
  round 0.4 smd mask+0.08: A1(-5.6,5.6) A2(-4.8,5.6) A3(-4,5.6) A4(-3.2,5.6) A5(-2.4,5.6) A6(-1.6,5.6) A7(-0.8,5.6) A8(0,5.6) A9(0.8,5.6) A10(1.6,5.6) A11(2.4,5.6) A12(3.2,5.6) A13(4,5.6) A14(4.8,5.6) A15(5.6,5.6) B1(-5.6,4.8) B2(-4.8,4.8) B3(-4,4.8) B4(-3.2,4.8) B5(-2.4,4.8) B6(-1.6,4.8) B7(-0.8,4.8) B8(0,4.8) B9(0.8,4.8) B10(1.6,4.8) B11(2.4,4.8) B12(3.2,4.8) B13(4,4.8) B14(4.8,4.8) B15(5.6,4.8) C1(-5.6,4) C2(-4.8,4) C3(-4,4) C4(-3.2,4) C5(-2.4,4) C6(-1.6,4) C7(-0.8,4) C8(0,4) C9(0.8,4) C10(1.6,4) C11(2.4,4) C12(3.2,4) C13(4,4) C14(4.8,4) C15(5.6,4) D1(-5.6,3.2) D2(-4.8,3.2) D3(-4,3.2) D4(-3.2,3.2) D5(-2.4,3.2) D6(-1.6,3.2) D7(-0.8,3.2) D8(0,3.2) D9(0.8,3.2) D10(1.6,3.2) D11(2.4,3.2) D12(3.2,3.2) D13(4,3.2) D14(4.8,3.2) D15(5.6,3.2) E1(-5.6,2.4) E2(-4.8,2.4) E3(-4,2.4) E4(-3.2,2.4) E5(-2.4,2.4) E6(-1.6,2.4) E7(-0.8,2.4) E8(0,2.4) E9(0.8,2.4) E10(1.6,2.4) E11(2.4,2.4) E12(3.2,2.4) E13(4,2.4) E14(4.8,2.4) E15(5.6,2.4) F1(-5.6,1.6) F2(-4.8,1.6) F3(-4,1.6) F4(-3.2,1.6) F5(-2.4,1.6) F6(-1.6,1.6) F7(-0.8,1.6) F8(0,1.6) F9(0.8,1.6) F10(1.6,1.6) F11(2.4,1.6) F12(3.2,1.6) F13(4,1.6) F14(4.8,1.6) F15(5.6,1.6) G1(-5.6,0.8) G2(-4.8,0.8) G3(-4,0.8) G4(-3.2,0.8) G5(-2.4,0.8) G6(-1.6,0.8) G7(-0.8,0.8) G8(0,0.8) G9(0.8,0.8) G10(1.6,0.8) G11(2.4,0.8) G12(3.2,0.8) G13(4,0.8) G14(4.8,0.8) G15(5.6,0.8) H1(-5.6,0) H2(-4.8,0) H3(-4,0) H4(-3.2,0) H5(-2.4,0) H6(-1.6,0) H7(-0.8,0) H8(0,0) H9(0.8,0) H10(1.6,0) H11(2.4,0) H12(3.2,0) H13(4,0) H14(4.8,0) H15(5.6,0) J1(-5.6,-0.8) J2(-4.8,-0.8) J3(-4,-0.8) J4(-3.2,-0.8) J5(-2.4,-0.8) J6(-1.6,-0.8) J7(-0.8,-0.8) J8(0,-0.8) J9(0.8,-0.8) J10(1.6,-0.8) J11(2.4,-0.8) J12(3.2,-0.8) J13(4,-0.8) J14(4.8,-0.8) J15(5.6,-0.8) K1(-5.6,-1.6) K2(-4.8,-1.6) K3(-4,-1.6) K4(-3.2,-1.6) K5(-2.4,-1.6) K6(-1.6,-1.6) K7(-0.8,-1.6) K8(0,-1.6) K9(0.8,-1.6) K10(1.6,-1.6) K11(2.4,-1.6) K12(3.2,-1.6) K13(4,-1.6) K14(4.8,-1.6) K15(5.6,-1.6) L1(-5.6,-2.4) L2(-4.8,-2.4) L3(-4,-2.4) L4(-3.2,-2.4) L5(-2.4,-2.4) L6(-1.6,-2.4) L7(-0.8,-2.4) L8(0,-2.4) L9(0.8,-2.4) L10(1.6,-2.4) L11(2.4,-2.4) L12(3.2,-2.4) L13(4,-2.4) L14(4.8,-2.4) L15(5.6,-2.4) M1(-5.6,-3.2) M2(-4.8,-3.2) M3(-4,-3.2) M4(-3.2,-3.2) M5(-2.4,-3.2) M6(-1.6,-3.2) M7(-0.8,-3.2) M8(0,-3.2) M9(0.8,-3.2) M10(1.6,-3.2) M11(2.4,-3.2) M12(3.2,-3.2) M13(4,-3.2) M14(4.8,-3.2) M15(5.6,-3.2) N1(-5.6,-4) N2(-4.8,-4) N3(-4,-4) N4(-3.2,-4) N5(-2.4,-4) N6(-1.6,-4) N7(-0.8,-4) N8(0,-4) N9(0.8,-4) N10(1.6,-4) N11(2.4,-4) N12(3.2,-4) N13(4,-4) N14(4.8,-4) N15(5.6,-4) P1(-5.6,-4.8) P2(-4.8,-4.8) P3(-4,-4.8) P4(-3.2,-4.8) P5(-2.4,-4.8) P6(-1.6,-4.8) P7(-0.8,-4.8) P8(0,-4.8) P9(0.8,-4.8) P10(1.6,-4.8) P11(2.4,-4.8) P12(3.2,-4.8) P13(4,-4.8) P14(4.8,-4.8) P15(5.6,-4.8) R1(-5.6,-5.6) R2(-4.8,-5.6) R3(-4,-5.6) R4(-3.2,-5.6) R5(-2.4,-5.6) R6(-1.6,-5.6) R7(-0.8,-5.6) R8(0,-5.6) R9(0.8,-5.6) R10(1.6,-5.6) R11(2.4,-5.6) R12(3.2,-5.6) R13(4,-5.6) R14(4.8,-5.6) R15(5.6,-5.6)
  silkscreen extent -6.65,6.55 -6.56,6.65, body extent -6.5,-6.5 6.5,6.5, height 1.2
CAP-0201 [mm] "Chip Capacitor, 2-Leads, Body 0201 (in) 0603 (mm) IPC Medium Density"
  rrect52% 0.31x0.34 smd mask+0.05: 1(-0.275,0) 2(0.275,0)
  body extent -0.3,-0.15 0.3,0.15, height 0.3
CAP-0402 [mm] "Chip Capacitor, 2-Leads, Body  0402 (in) 1005 (mm), IPC Medium Density"
  rrect52% 0.63x0.58 smd mask+0.05: 1(-0.435,0) 2(0.435,0)
  body extent -0.5,-0.25 0.5,0.25, height 0.5
CAP-0603 [mm] "Chip Capacitor, Body 0603 imperial,1.6x0.8mm, IPC High Density"
  rrect51% 0.87x0.97 smd mask+0.05: 1(-0.75,0) 2(0.75,0)
  body extent -0.8,-0.4 0.8,0.4, height 0.8
CAP-0805 [mm] "Chip Capacitor, Body 0805 imperial, 2.0x1.2mm, IPC Medium Density"
  rrect45% 1.11x1.47 smd mask+0.05: 1(-0.85,0) 2(0.85,0)
  body extent -1,-0.62 1,0.63, height 1.25
CAP-1206 [mm] "Chip Capacitor, 2-Leads, 1206 (in) 3216 (mm), IPC Medium Density"
  rrect43% 1.16x1.82 smd mask+0.05: 1(-1.475,0) 2(1.475,0)
  body extent -1.6,-0.8 1.6,0.8, height 1.6
CRYSTAL3.2X2.5 [mm]
  rrect10% 1.3x1.1 smd: 1(-1.15,-0.9) 2(1.15,-0.9) 3(1.15,0.9) 4(-1.15,0.9)
  body extent -1.65,-1.14 1.52,1.27, height 0.6
CSEC202-3002A001C1AF [mm]
  rect 0.65x2.15 smd: 1(-18.415,-1.825) 2(-18.415,1.824) 3(-17.145,-1.825) 4(-17.145,1.824) 5(-15.875,-1.825) 6(-15.875,1.824) 7(-14.605,-1.825) 8(-14.605,1.824) 9(-13.335,-1.825) 10(-13.335,1.824) 11(-12.065,-1.825) 12(-12.065,1.824) 13(-10.795,-1.825) 14(-10.795,1.824) 15(-9.525,-1.825) 16(-9.525,1.824) 17(-8.255,-1.825) 18(-8.255,1.824) 19(-6.985,-1.825) 20(-6.985,1.824) 21(-5.715,-1.825) 22(-5.715,1.824) 23(-4.445,-1.825) 24(-4.445,1.824) 25(-3.175,-1.825) 26(-3.175,1.824) 27(-1.905,-1.825) 28(-1.905,1.824) 29(-0.635,-1.825) 30(-0.635,1.824) 31(0.635,-1.825) 32(0.635,1.824) 33(1.905,-1.825) 34(1.905,1.824) 35(3.175,-1.825) 36(3.175,1.824) 37(4.445,-1.825) 38(4.445,1.824) 39(5.715,-1.825) 40(5.715,1.824) 41(6.985,-1.825) 42(6.985,1.824) 43(8.255,-1.825) 44(8.255,1.824) 45(9.525,-1.825) 46(9.525,1.824) 47(10.795,-1.825) 48(10.795,1.824) 49(12.065,-1.825) 50(12.065,1.824) 51(13.335,-1.825) 52(13.335,1.824) 53(14.605,-1.825) 54(14.605,1.824) 55(15.875,-1.825) 56(15.875,1.824) 57(17.145,-1.825) 58(17.145,1.824) 59(18.415,-1.825) 60(18.415,1.824)
  silkscreen extent -18.46,-3.35 -18.36,-3.25, body extent -19.11,-2.3 19.11,2.3, height 4.55
CSEC202-5002A001C1AF [mm]
  rect 0.65x2.15 smd: 1(-31.115,1.825) 2(-31.115,-1.825) 3(-29.845,1.825) 4(-29.845,-1.825) 5(-28.575,1.825) 6(-28.575,-1.825) 7(-27.305,1.825) 8(-27.305,-1.825) 9(-26.035,1.825) 10(-26.035,-1.825) 11(-24.765,1.825) 12(-24.765,-1.825) 13(-23.495,1.825) 14(-23.495,-1.825) 15(-22.225,1.825) 16(-22.225,-1.825) 17(-20.955,1.825) 18(-20.955,-1.825) 19(-19.685,1.825) 20(-19.685,-1.825) 21(-18.415,1.825) 22(-18.415,-1.825) 23(-17.145,1.825) 24(-17.145,-1.825) 25(-15.875,1.825) 26(-15.875,-1.825) 27(-14.605,1.825) 28(-14.605,-1.825) 29(-13.335,1.825) 30(-13.335,-1.825) 31(-12.065,1.825) 32(-12.065,-1.825) 33(-10.795,1.825) 34(-10.795,-1.825) 35(-9.525,1.825) 36(-9.525,-1.825) 37(-8.255,1.825) 38(-8.255,-1.825) 39(-6.985,1.825) 40(-6.985,-1.825) 41(-5.715,1.825) 42(-5.715,-1.825) 43(-4.445,1.825) 44(-4.445,-1.825) 45(-3.175,1.825) 46(-3.175,-1.825) 47(-1.905,1.825) 48(-1.905,-1.825) 49(-0.635,1.825) 50(-0.635,-1.825) 51(0.635,1.825) 52(0.635,-1.825) 53(1.905,1.825) 54(1.905,-1.825) 55(3.175,1.825) 56(3.175,-1.825) 57(4.445,1.825) 58(4.445,-1.825) 59(5.715,1.825) 60(5.715,-1.825) 61(6.985,1.825) 62(6.985,-1.825) 63(8.255,1.825) 64(8.255,-1.825) 65(9.525,1.825) 66(9.525,-1.825) 67(10.795,1.825) 68(10.795,-1.825) 73(14.605,1.825) 74(14.605,-1.825) 75(15.875,1.825) 76(15.875,-1.825) 77(17.145,1.825) 78(17.145,-1.825) 79(18.415,1.825) 80(18.415,-1.825) 81(19.685,1.825) 82(19.685,-1.825) 83(20.955,1.825) 84(20.955,-1.825) 85(22.225,1.825) 86(22.225,-1.825) 87(23.495,1.825) 88(23.495,-1.825) 89(24.765,1.825) 90(24.765,-1.825) 91(26.035,1.825) 92(26.035,-1.825) 93(27.305,1.825) 94(27.305,-1.825) 95(28.575,1.825) 96(28.575,-1.825) 97(29.845,1.825) 98(29.845,-1.825) 99(31.115,1.825) 100(31.115,-1.825)
  rect 0.65x1.95 smd: 69(12.065,1.925) 70(12.065,-1.924) 71(13.335,1.925) 72(13.335,-1.924)
  silkscreen extent -31.16,3.27 -31.07,3.37, body extent -31.93,-2.4 31.93,2.4, height 4.6
CX90B2-24P [mm] "CONN USB TYPEC"
  rect 0.25x0.65 smd mask+0.04: A1(-2.625,2.426) A2(-2.125,2.426) A3(-1.625,2.426) A4(-1.125,2.426) A5(-0.625,2.426) A6(-0.125,2.426) A7(0.375,2.426) A8(0.875,2.426) A9(1.375,2.426) A10(1.875,2.426) A11(2.375,2.426) A12(2.875,2.426) B1(2.625,0.926) B2(2.125,0.926) B3(1.625,0.926) B4(1.125,0.926) B5(0.625,0.926) B6(0.125,0.925) B7(-0.375,0.926) B8(-0.875,0.926) B9(-1.375,0.926) B10(-1.875,0.926) B11(-2.375,0.926) B12(-2.875,0.926)
  rect 0.27x0.65 smd mask+0.04: FIXING(-3.385,0.926) FIXING(3.385,0.926)
  oval 1.2x2.2 hole 0.6 slot 1.6 at 90 deg mask+0.05: SHIELD1(-4.32,2.001) SHIELD2(4.32,2.001) SHIELD3(-4.32,-3.099) SHIELD4(4.32,-3.099)
  body extent -4.47,-5.46 4.47,2.69, height 3.17
DF2B7ASL,L3F [mm] "SL2 0.62 x 0.32 x 0.3mm"
  rect 0.26x0.25 smd mask+0.05: 1(-0.225,0) 2(0.225,0)
  body extent -0.31,-0.16 0.31,0.16, height 0.3
DG127-5.0-05P-13-00Z(H) [mm]
  round 2.2 hole 1.3 mask+0.05: 1(-10,0) 2(-5,0) 3(0,0) 4(5,0) 5(10,0)
  silkscreen extent -10.49,1.47 10.51,2.47, body extent -12.5,-4 13,4.1, height 10
"Fiducial mark 1mm with circle-Footprint-1" [mm]
  round 1 smd paste-10 mask+0.5: 1(0,0)
  TOP_L1 pour cut-out: 0,1 0.383,0.924 0.707,0.707 0.924,0.383 1,0 1,0 0.924,-0.383 0.707,-0.707 0.383,-0.924 0,-1 0,-1 -0.383,-0.924 -0.707,-0.707 -0.924,-0.383 -1,0 -1,0 -0.924,0.383 -0.707,0.707 -0.383,0.924 0,1
"INDUCTOR 2520" [mm] "Chip Inductor, 2-Leads, Body 2,50x2,00mm, IPC Medium Density"
  rrect10% 0.8x2 smd mask+0.05: 1(-1,0) 2(1,0)
  body extent -1.35,-1.1 1.35,1.1, height 1.2
"Inductor 5030" [mm] "Inductor 5x5mm height 3mm"
  rect 4.2x1.4 smd mask+0.05: 1(0,-1.85) 2(0,1.85)
  body extent -2.54,-2.5 2.5,2.5, height 3
L-0402 [mm] "Chip Inductor, 2-Leads, Body 0402 (in)"
  rrect51% 0.55x0.58 smd mask+0: 1(-0.475,0) 2(0.475,0)
  body extent -0.5,-0.25 0.5,0.25, height 0.34
LEDC1608X80N-AK [mm]
  rrect50% 0.72x0.87 smd: A(0.725,0) C(-0.725,0)
  body extent -0.8,-0.4 0.8,0.4, height 0.79
LQM2MPN2R2NG0L [mm]
  rrect48% 1.05x1.72 smd paste+0 mask+0.05: 1(-0.785,0) 2(0.785,0)
  body extent -1,-0.8 1,0.8, height 0.9
MDT580M01001 [mm]
  rect 0.3x1.55 smd mask+0.05: 1(-9.25,3.779) 2(-9,-3.771) 3(-8.75,3.779) 4(-8.5,-3.771) 5(-8.25,3.779) 6(-8,-3.771) 7(-7.75,3.779) 8(-7.5,-3.771) 9(-7.25,3.779) 10(-7,-3.771) 11(-6.75,3.779) 12(-6.5,-3.771) 13(-6.25,3.779) 14(-6,-3.771) 15(-5.75,3.779) 16(-5.5,-3.771) 17(-5.25,3.779) 18(-5,-3.771) 19(-4.75,3.779) 20(-4.5,-3.771) 21(-4.25,3.779) 22(-4,-3.771) 23(-3.75,3.779) 24(-3.5,-3.771) 25(-3.25,3.779) 26(-3,-3.771) 27(-2.75,3.779) 28(-2.5,-3.771) 29(-2.25,3.779) 30(-2,-3.771) 31(-1.75,3.779) 32(-1.5,-3.771) 33(-1.25,3.779) 34(-1,-3.771) 35(-0.75,3.779) 36(-0.5,-3.771) 37(-0.25,3.779) 38(0,-3.771) 39(0.25,3.779) 40(0.5,-3.771) 41(0.75,3.779) 42(1,-3.771) 43(1.25,3.779) 44(1.5,-3.771) 45(1.75,3.779) 46(2,-3.771) 47(2.25,3.779) 48(2.5,-3.771) 49(2.75,3.779) 50(3,-3.771) 51(3.25,3.779) 52(3.5,-3.771) 53(3.75,3.779) 54(4,-3.771) 55(4.25,3.779) 56(4.5,-3.771) 57(4.75,3.779) 58(5,-3.771) 67(7.25,3.779) 68(7.5,-3.771) 69(7.75,3.779) 70(8,-3.771) 71(8.25,3.779) 72(8.5,-3.771) 73(8.75,3.779) 74(9,-3.771) 75(9.25,3.779)
  rect 1.2x2.75 smd mask+0.05: FIXING(-10.35,3.004) FIXING(10.35,3.004)
  round 0 hole 1.6 unplated: MH1(10,-1.496)
  round 0 hole 1.1 unplated: MH2(-10,-1.496)
  body extent -11,-4.26 11,4.26, height 5.75
"Microchip VDFN8 pitch 0.65mm 3x3mm exposed pad 2.4x1.6mm" [mm]
  rrect25% 0.8x0.35 smd mask+0.05: 1(-1.5,0.975) 2(-1.5,0.325) 3(-1.5,-0.325) 4(-1.5,-0.975) 5(1.5,-0.975) 6(1.5,-0.325) 7(1.5,0.325) 8(1.5,0.975)
  round 0.025 smd paste-2539.97 mask+0.05: 9(0,0)
  silkscreen extent -1.7,1.6 -1.6,1.7, body extent -1.5,-1.5 1.5,1.5, height 1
